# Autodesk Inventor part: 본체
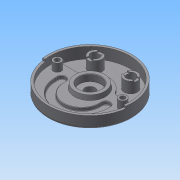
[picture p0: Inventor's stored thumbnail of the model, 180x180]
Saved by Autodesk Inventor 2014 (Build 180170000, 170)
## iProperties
Created: 2015-06
Part Number: 본체
Material: Generic
Document SubType Name: Modeling
Designer: Administrator
Density: 1 g/cm^3
Appearance: Default
Author: Administrator
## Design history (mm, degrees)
sketch "스케치1"
  geometry: C1 r 95 at (0, 0); 1 further point
  constraints: 1 centre point, 1 coincident
  dimensions: "d0" = 190 diameter of C1
extrude "돌출1" new body sketch "스케치1" distance "d1" = 32; taper "d2" = 0 deg
sketch "스케치2"
  geometry: C1 r 95 at (0, 0) reference; C2 r 90 at (0, 0)
  constraints: 1 centre point, 1 coincident
  dimensions: "d3" = 180 diameter of C2
extrude "돌출2" cut sketch "스케치2" distance "d4" = 18; taper "d5" = 0 deg
sketch "스케치3"
  geometry: L1 (-38.833, 16)-(-88.566, 16); L2 (38.833, 16)-(88.566, 16); A1 r 90 centre (0, 0) between (-88.566, 16) and (88.566, 16) reference; A2 r 42 centre (0, 0) between (-38.833, 16) and (38.833, 16)
  constraints: 4 end point, 4 point on circle, 1 centre point, 1 coincident, 1 collinear, 1 horizontal, 1 point on line
  dimensions: "d6" = 84 diameter of A2; "d7" = 16 distance from line of L1 A1.centre
extrude "돌출3" cut sketch "스케치3" distance "d8" = 7; taper "d9" = 0 deg
sketch "스케치4"
  geometry: C1 r 35 at (0, 0); A1 r 42 centre (0, 0) between (38.833, 16) and (-38.833, 16) reference
  constraints: 1 centre point, 1 coincident
  dimensions: "d10" = 70 diameter of C1
extrude "돌출4" join sketch "스케치4" distance "d11" = 10; taper "d12" = -10 deg
sketch "스케치5"
  geometry: L1 (-95, 0)-(95, 0); L2 (0, 0)-(-94.075, -13.221); L3 (0, 0)-(94.075, -13.221); C1 r 90 at (0, 0) reference; A1 r 95 centre (0, 0) between (-95, 0) and (95, 0) reference
  constraints: 6 end point, 4 point on circle, 1 coincident, 1 horizontal, 1 midpoint
  dimensions: "d13" = 8 deg angle of L2 L1; "d14" = 8 deg angle of L3 L1
extrude "돌출5" cut sketch "스케치5" distance "d15" = 5; taper "d16" = 0 deg
sketch "스케치6"
  geometry: L1 (88.566, 16)-(38.833, 16) reference; L2 (-74, 0)-(74, 0); C1 r 35 at (0, 0) reference; C2 r 9 at (-74, 0); C3 r 9 at (74, 0); 1 further point
  constraints: 3 coincident, 2 centre point, 2 end point, 1 midpoint, 1 parallel
  dimensions: "d17" = 148 distance of L2.start L2.end; "d18" = 18 diameter of C2; "d19" = 18 diameter of C3
extrude "돌출6" join sketch "스케치6" stored distance "d20" = 0; taper "d21" = 0 deg
sketch "스케치7"
  geometry: L1 (88.566, 16)-(38.833, 16) reference; L2 (-87.972, -19)-(87.972, -19); L3 (-88.904, -14)-(88.904, -14); L4 (-59, -19)-(-59, -14); L5 (-41, -19)-(-41, -14); L6 (41, -19)-(41, -14); L7 (59, -19)-(59, -14); C1 r 35 at (0, 0) reference; A1 r 90 centre (0, 0) between (-88.566, 16) and (88.566, 16) reference; A2 r 59 centre (0, -19) between (-59, -19) and (59, -19); A3 r 41 centre (0, -19) between (-41, -19) and (41, -19); A4 r 9 centre (-50, -14) between (-41, -14) and (-59, -14); A5 r 9 centre (50, -14) between (59, -14) and (41, -14); 1 further point
  constraints: 12 end point, 11 point on circle, 8 point on line, 8 tangent, 4 centre point, 4 parallel, 2 perpendicular, 1 coincident, 1 midpoint, 1 vertical alignment
  dimensions: "d22" = 118 diameter of A2; "d23" = 19 distance of A2.centre C1.centre; "d24" = 82 diameter of A3; "d25" = 5 distance between parallel lines of L2 L3
extrude "돌출7" cut sketch "스케치7" distance "d26" = 7; taper "d27" = 0 deg
sketch "스케치8"
  geometry: L1 (-38.833, 16)-(-88.566, 16) reference; L2 (-40, 52)-(40, 52); C1 r 15 at (-40, 52); C2 r 15 at (40, 52); A1 r 42 centre (0, 0) between (38.833, 16) and (-38.833, 16) reference; 1 further point
  constraints: 2 centre point, 2 coincident, 2 end point, 1 equal radius, 1 midpoint, 1 parallel, 1 vertical alignment
  dimensions: "d28" = 80 distance of L2.start L2.end; "d29" = 52 distance from line of L2 A1.centre; "d30" = 30 diameter of C1
extrude "돌출8" join sketch "스케치8" stored distance "d31" = 7; taper "d32" = 0 deg
sketch "스케치9"
  geometry: C1 r 95 at (0, 0) reference; C2 r 26 at (0, 0)
  constraints: 1 centre point, 1 coincident
  dimensions: "d33" = 52 diameter of C2
extrude "돌출9" join sketch "스케치9" distance "d34" = 12; taper "d35" = -15 deg
hole "구멍1" diameter "d38" = 23; stored, may be unused: countersink angle "d42" = 90 deg, drill point angle "d44" = 0 deg; dims "d36" = 10, "d37" = 10, "d39" = 6, "d40" = 50, "d41" = 15, "d43" = 8
sketch "스케치10"
  geometry: C1 r 15 at (0, 0) reference; C2 r 15 at (80, 0) reference; 3 further points
  constraints: 2 coincident
hole "구멍2" sketch "스케치10" at (0, 0), (80, 0) diameter "d45" = 20; stored, may be unused: countersink angle "d49" = 90 deg, drill point angle "d51" = 0 deg; dims "d46" = 6, "d47" = 50, "d48" = 15, "d50" = 8
sketch "스케치11"
  geometry: C1 r 9 at (-74, 0) reference; C2 r 9 at (74, 0) reference; 2 further points
  constraints: 2 coincident
hole "구멍3" sketch "스케치11" at (-74, 0), (74, 0) diameter "d52" = 11; stored, may be unused: countersink angle "d56" = 90 deg, drill point angle "d58" = 0 deg; dims "d53" = 6, "d54" = 18, "d55" = 11, "d57" = 8
sketch "스케치12"
  geometry: C1 r 95 at (0, 0) reference; C2 r 68 at (0, 0)
  constraints: 1 centre point, 1 coincident, 1 other
  dimensions: "d59" = 136 diameter of C2
feature "엠보싱1" sketch "스케치12" dims "d60" = 0.5, "d61" = 0
sketch "스케치13"
  geometry: L1 (-6, 13.748)-(-6, -13.748); L2 (6, 13.748)-(6, -13.748); L3 (66.252, 6)-(93.748, 6); L4 (66.252, -6)-(93.748, -6); C1 r 10 at (80, 0) reference; A1 r 15 centre (0, 0) between (-6, 13.748) and (-6, -13.748) reference; A2 r 15 centre (80, 0) between (66.252, 6) and (93.748, 6) reference; 1 further point
  constraints: 8 end point, 8 point on circle, 4 parallel, 1 perpendicular, 1 vertical
  dimensions: "d62" = 12 distance between parallel lines of L2 L1; "d63" = 12 distance between parallel lines of L4 L3
extrude "돌출10" cut sketch "스케치13" distance "d64" = 3; taper "d65" = 0 deg
chamfer "모따기1" distance "d66" = 1; stored, may be unused: second distance "d67" = 2, angle "d68" = 45 deg
fillet "모깎기1" dims "d69" = 10
fillet "모깎기2" dims "d70" = 10
fillet "모깎기3" dims "d71" = 5, "d72" = 1
fillet "모깎기4" dims "d73" = 0.3
node "솔리드1"
node "투영된 루프1"
